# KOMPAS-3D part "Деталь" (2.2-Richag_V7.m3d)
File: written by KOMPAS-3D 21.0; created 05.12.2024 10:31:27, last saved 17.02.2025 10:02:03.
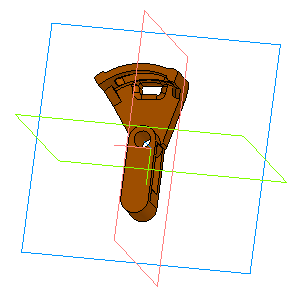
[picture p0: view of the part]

Document properties: Автор: Admin; Полное имя файла: Z:\!_Силкин\!!!_Дрон\Autel Robotics EVO Lite\Подвес\EVO\V6\под\под\2.2-Richag_V7.m3d

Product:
- Part/product: Деталь
    Масса: 0.012889

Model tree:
1. Эскиз:1
2. Элемент выдавливания:1
     Расстояние 1 = 2
3. Эскиз:2  (with: Элемент выдавливания:1)
4. Элемент выдавливания:2
     Расстояние 1 = 1.5
5. Эскиз:6  (with: Элемент выдавливания:1)
6. Элемент выдавливания:9
     Расстояние 2 = 10
7. Эскиз:9  (with: Элемент выдавливания:9, Элемент выдавливания:1)
8. Элемент выдавливания:10  (with: Элемент выдавливания:1)
     Расстояние 2 = 8
9. Эскиз:11  (with: Элемент выдавливания:9, Элемент выдавливания:10)
10. Элемент выдавливания:12
     Расстояние 2 = 2
11. Эскиз:12  (with: Элемент выдавливания:2)
12. Элемент выдавливания:13
     Расстояние 1 = 1
13. Эскиз:13  (with: Элемент выдавливания:1)
14. Элемент выдавливания:14
     Расстояние 1 = 2.5
15. Элемент выдавливания:15  (with: Элемент выдавливания:13)
     Расстояние 1 = 1
16. Эскиз:14  (with: Элемент выдавливания:1, Элемент выдавливания:2)
17. Элемент выдавливания:17  (with: Элемент выдавливания:1)
     Расстояние 2 = 2
18. Эскиз:15  (with: Элемент выдавливания:1)
19. Элемент выдавливания:18
     Расстояние 2 = 10
20. Эскиз:16  (with: Элемент выдавливания:1, Элемент выдавливания:18)
21. Элемент выдавливания:19  (with: Элемент выдавливания:1)
     Расстояние 1 = -2
22. Скругление:1  (with: Элемент выдавливания:19)
     Радиус = 3
23. Эскиз:17  (with: Элемент выдавливания:1, Элемент выдавливания:2, Элемент выдавливания:14)
24. Элемент выдавливания:20  (with: Элемент выдавливания:15)
     Расстояние 1 = 3.5
25. Эскиз:18  (with: Элемент выдавливания:1)
26. Элемент выдавливания:21
     Расстояние 1 = 10; Расстояние 2 = 10
27. Эскиз:19  (with: Элемент выдавливания:1, Элемент выдавливания:21, Элемент выдавливания:17)
28. Элемент выдавливания:22  (with: Элемент выдавливания:1)
     Расстояние 2 = 2
29. Эскиз:20  (with: Элемент выдавливания:1, Элемент выдавливания:9, Элемент выдавливания:17, Элемент выдавливания:22)
30. Элемент выдавливания:23  (with: Элемент выдавливания:9)
     Расстояние 1 = 8
31. Эскиз:21  (with: Элемент выдавливания:1)
32. Элемент выдавливания:24  (with: Элемент выдавливания:12)
     Расстояние 2 = 8
33. Эскиз:22  (with: Элемент выдавливания:9, Элемент выдавливания:23)
34. Элемент выдавливания:25
     Расстояние 1 = 10
35. Эскиз:23  (with: Элемент выдавливания:24, Элемент выдавливания:25)
36. Элемент выдавливания:26
     Расстояние 2 = 6
37. Скругление:2  (with: Элемент выдавливания:25)
     Радиус = 3
38. Скругление:3  (with: Элемент выдавливания:26)
     Радиус = 2
39. Скругление:4  (with: Элемент выдавливания:23)
     Радиус = 2
40. Эскиз:24  (with: Элемент выдавливания:25)
41. Элемент выдавливания:27
     Расстояние 2 = 10
42. Эскиз:25  (with: Элемент выдавливания:25, Элемент выдавливания:27)
43. Элемент выдавливания:28  (with: Элемент выдавливания:26)
     Расстояние 2 = 6
44. Эскиз:26  (with: Элемент выдавливания:25, Элемент выдавливания:27)
45. Элемент выдавливания:29  (with: Элемент выдавливания:26)
     Расстояние 2 = 6
46. Эскиз:27  (with: Элемент выдавливания:25)
47. Элемент выдавливания:30
     Расстояние 2 = 10
48. Скругление:5  (with: Элемент выдавливания:28, Элемент выдавливания:22, Элемент выдавливания:29)
     Радиус = 0.5
49. Скругление:6  (with: Элемент выдавливания:30, Элемент выдавливания:28)
     Радиус = 3
50. Скругление:7  (with: Элемент выдавливания:29, Элемент выдавливания:22)
     Радиус = 1
51. Эскиз:28  (with: Элемент выдавливания:9, Элемент выдавливания:12)
52. Элемент выдавливания:31
     Расстояние 2 = 7
53. Эскиз:29  (with: Элемент выдавливания:9, Элемент выдавливания:31)
54. Эскиз:30  (with: Элемент выдавливания:25)
55. Элемент выдавливания:32
     Расстояние 2 = 10
56. Элемент выдавливания:33
     Расстояние 2 = 5
57. Элемент выдавливания:34
     Расстояние 1 = 4
58. Элемент выдавливания:35  (with: Элемент выдавливания:34)
     Расстояние 2 = 5.4
59. Эскиз:31  (with: Элемент выдавливания:35)
60. Элемент выдавливания:36
     Расстояние 2 = 3.25
61. Скругление:8  (with: Элемент выдавливания:36)
     Радиус = 1.5
62. Эскиз:32  (with: Элемент выдавливания:33, Элемент выдавливания:36)
63. Элемент выдавливания:37
     Расстояние 2 = 10
64. Эскиз:33  (with: Элемент выдавливания:9, Элемент выдавливания:12)
65. Элемент выдавливания:38  (with: Элемент выдавливания:33)
     Расстояние 2 = 5
66. Элемент выдавливания:43  (with: Элемент выдавливания:35)
     Расстояние 1 = 3.3
67. Элемент выдавливания:44  (with: Элемент выдавливания:35)
     Расстояние 1 = 3.3
68. Эскиз:34  (with: Элемент выдавливания:43)
69. Элемент выдавливания:45
     Расстояние 1 = 3
70. Скругление:9  (with: Элемент выдавливания:45)
     Радиус = 1.5
71. Элемент выдавливания:51  (with: Элемент выдавливания:31, Элемент выдавливания:1)
     Расстояние 1 = 3
72. Эскиз:39  (with: Элемент выдавливания:1, Элемент выдавливания:10)
73. Элемент выдавливания:52  (with: Элемент выдавливания:12)
     Расстояние 1 = 6
74. Скругление:13  (with: Элемент выдавливания:33)
     Радиус = 0.5
75. Эскиз:40  (with: Элемент выдавливания:31)
76. Элемент выдавливания:53
     Расстояние 2 = 2
77. Эскиз:41  (with: Элемент выдавливания:31)
78. Элемент выдавливания:54
     Расстояние 2 = 2
79. Скругление:14  (with: Элемент выдавливания:37)
     Радиус = 1.3
80. Эскиз:42  (with: Элемент выдавливания:45, Элемент выдавливания:33)
81. Элемент выдавливания:55  (with: Элемент выдавливания:1)
     Расстояние 2 = 14.9
82. Эскиз:44  (with: Элемент выдавливания:31, Элемент выдавливания:33, Элемент выдавливания:45)
83. Элемент выдавливания:57
     Расстояние 2 = 2
84. Скругление:18  (with: Элемент выдавливания:57)
     Радиус = 1
85. Скругление:19  (with: Элемент выдавливания:54)
     Радиус = 1
86. Скругление:21  (with: Элемент выдавливания:31)
     Радиус = 1
87. Скругление:22  (with: Элемент выдавливания:52)
     Радиус = 0.3
88. Фаска:4  (with: Элемент выдавливания:1)
     Угол = 45; Длина 1 = 0.5; Длина 2 = 0.5
89. Скругление:25  (with: Элемент выдавливания:51)
     Радиус = 3.5
90. Скругление:27  (with: Элемент выдавливания:55)
     Радиус = 1
91. Скругление:28  (with: Элемент выдавливания:55)
     Радиус = 1
92. Скругление:30  (with: Элемент выдавливания:55)
     Радиус = 4
93. Эскиз:46  (with: Элемент выдавливания:9)
94. Элемент выдавливания:58
     Расстояние 2 = 10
